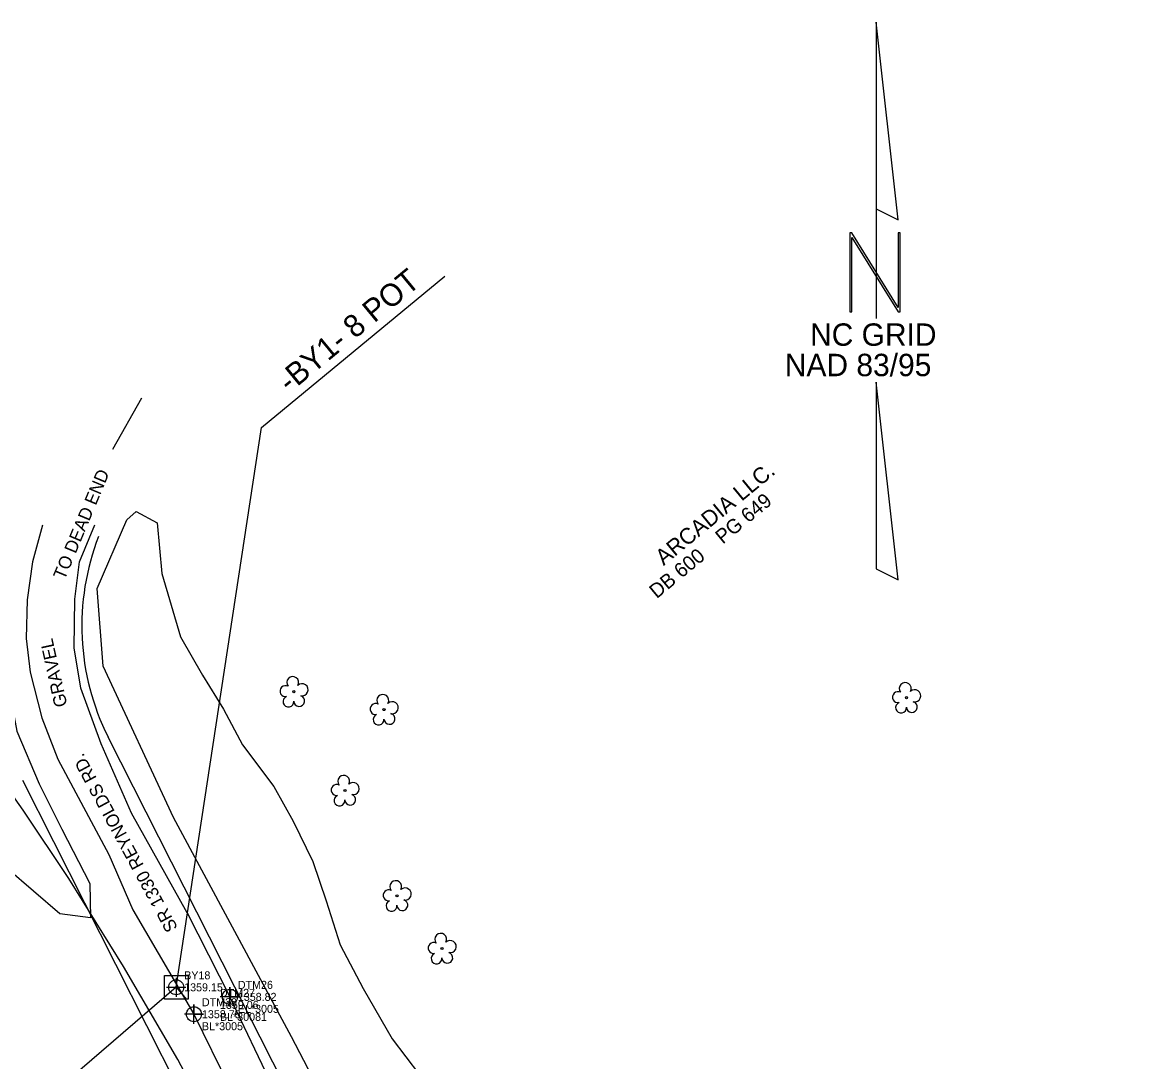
# Model space of a CAD drawing. Extents: x 1435573 to 1437263, y 981340 to 982884.
# Drawn here: x 1436335.7 to 1436683.9, y 982559.5 to 982884.4 of the extents above; entities that cross this region are included whole.
import ezdxf

# ---------------------------------------------------------------- set-up
doc = ezdxf.new("R2010")
doc.units = 0
for name, color, linetype in [('Cogo Default Point CELL', 7, 'Continuous'), ('COGO Default Point Elevation', 7, 'Continuous'), ('COGO Default Point Number', 7, 'Continuous'), ('CTL North Arrow NAD 83 95 CELL', 7, 'Continuous'), ('CTL Supplemental Horizontal and Vertical CELL', 7, 'Continuous'), ('Exist DTM Crownline Cogo Comment', 7, 'Continuous'), ('Exist DTM Crownline Cogo Elevation', 7, 'Continuous'), ('Exist DTM Crownline Cogo Number', 7, 'Continuous'), ('Exist Horizontal Baseline Alignment', 7, 'Continuous'), ('Exist Horizontal Baseline Alignment Station Label', 7, 'Continuous'), ('Exist Horizontal Baseline Alignment Tick small', 7, 'Continuous'), ('Exist Other Culture Fence Line', 7, 'Continuous'), ('Exist Property Deed Book Text', 7, 'Continuous'), ('Exist Property Owner Text', 7, 'Continuous'), ('Exist Right of Way Line', 7, 'Continuous'), ('Exist Roads Soil', 7, 'Continuous'), ('Exist Roads Soil Cogo Comment', 7, 'Continuous'), ('Exist Roads Soil Cogo Elevation', 7, 'Continuous'), ('Exist Roads Soil Cogo Number', 7, 'Continuous'), ('Exist Roads Soil Cogo Point CELL', 7, 'Continuous'), ('Exist Roads Soil Leader', 7, 'Continuous'), ('Exist Roads Soil Text', 7, 'Continuous'), ('Exist Vegetation Tree CELL', 7, 'Continuous'), ('Exist Vegetation Woods Line', 7, 'Continuous')]:
    doc.layers.add(name, color=color, linetype=linetype)

# ---------------------------------------------------------------- blocks, each defined once
blk = doc.blocks.new('CTL SUPPLEMENTAL HORIZONTAL AND VERTICAL')
at = {"layer": 'CTL Supplemental Horizontal and Vertical CELL'}
blk.add_line((0, 0), (0, 0), dxfattribs=at)
blk.add_lwpolyline([(-0.0735, 0.074), (0.07475, 0.074), (0.07475, -0.0745), (-0.0735, -0.0745)], close=True, dxfattribs=at)
blk = doc.blocks.new('CTL NORTH ARROW NAD 83 95')
at = {"layer": 'CTL North Arrow NAD 83 95 CELL'}
for points in [[(-0.003, 1.7458), (-0.003, 0.5793), (0.1345, 0.5105)], [(-0.1675, -0.0653), (-0.1537, -0.0653), (-0.1537, 0.4012), (0.1345, -0.0653), (0.1482, -0.0653), (0.1482, 0.4285), (0.1345, 0.4285), (0.1345, -0.038), (-0.1537, 0.4285), (-0.1675, 0.4285)], [(-0.003, -1.671), (0.1345, -1.7392), (-0.003, -0.5045)]]:
    blk.add_lwpolyline(points, close=True, dxfattribs=at)
blk.add_lwpolyline([(-0.003, 0.5793), (-0.003, -0.1067)], dxfattribs=at)
for s, p in [('NC GRID', (-0.4154, -0.2767)), ('NAD 83/95', (-0.5731, -0.4667))]:
    blk.add_text(s, height=0.14, dxfattribs=at).set_placement(p)

msp = doc.modelspace()

# ---------------------------------------------------------------- linework, layer by layer
at = {"layer": 'Cogo Default Point CELL'}
for points in [[(1436383.8, 982585.77), (1436383.8, 982582.77)], [(1436380.8, 982582.77), (1436383.8, 982582.77)], [(1436383.8, 982582.77), (1436386.8, 982582.77)], [(1436383.8, 982582.77), (1436383.8, 982579.77)]]:
    msp.add_lwpolyline(points, dxfattribs=at)
msp.add_circle((1436383.8, 982582.77), 2.34, dxfattribs=at)
at = {"layer": 'Exist Horizontal Baseline Alignment'}
msp.add_line((1436383.8, 982582.77), (1436220.79, 982442.59), dxfattribs=at)
at = {"layer": 'Exist Horizontal Baseline Alignment Station Label'}
for p, q in [((1436410.49, 982757.79), (1436467.76, 982805.06)), ((1436383.8, 982582.77), (1436410.49, 982757.79))]:
    msp.add_line(p, q, dxfattribs=at)
at = {"layer": 'Exist Horizontal Baseline Alignment Tick small'}
msp.add_line((1436383.8, 982582.77), (1436387.06, 982578.98), dxfattribs=at)
at = {"layer": 'Exist Other Culture Fence Line'}
msp.add_lwpolyline([(1436407.45, 982513.75), (1436396.08, 982537.77), (1436384.33, 982560.23), (1436367.33, 982589.31), (1436350.22, 982616.82), (1436336.01, 982638.12), (1436324.12, 982654.83), (1436316.59, 982679.36), (1436311.21, 982691.99), (1436311.43, 982712.74), (1436311.84, 982730.67)], dxfattribs=at)
at = {"layer": 'Exist Right of Way Line'}
for p, q in [((1436362.49, 982661.08), (1436453.17, 982481.97)), ((1436335.73, 982647.53), (1436408.6, 982503.6))]:
    msp.add_line(p, q, dxfattribs=at)
msp.add_arc((1436431.59, 982695.7), 77.28, 158.7705, 206.6391, dxfattribs=at)
at = {"layer": 'Exist Roads Soil'}
for p, q in [((1436423.3, 982532.29), (1436400.57, 982579.79)), ((1436389.35, 982574.36), (1436412.81, 982526.49))]:
    msp.add_line(p, q, dxfattribs=at)
for points in [[(1436342.05, 982727.23), (1436338.86, 982715.75), (1436337.28, 982703.86), (1436336.9, 982691.84), (1436338.16, 982681.24), (1436341.87, 982667), (1436346.86, 982654.14), (1436354.05, 982640.61), (1436362.77, 982624.29), (1436370.25, 982607.02)], [(1436387.28, 982606.05), (1436369.84, 982637.26), (1436360.31, 982658.92), (1436354.03, 982676.29), (1436351.96, 982688.94), (1436352.09, 982704.07), (1436353.56, 982715.77), (1436358.41, 982727.38)], [(1436370.25, 982607.02), (1436389.35, 982574.36)], [(1436387.28, 982606.05), (1436400.57, 982579.79)]]:
    msp.add_lwpolyline(points, dxfattribs=at)
at = {"layer": 'Exist Roads Soil Cogo Point CELL'}
for points in [[(1436400.57, 982576.79), (1436400.57, 982582.79), (1436400.57, 982579.79), (1436403.57, 982579.79), (1436397.57, 982579.79)], [(1436389.35, 982571.36), (1436389.35, 982577.36), (1436389.35, 982574.36), (1436392.35, 982574.36), (1436386.35, 982574.36)]]:
    msp.add_lwpolyline(points, dxfattribs=at)
for centre in [(1436400.57, 982579.79), (1436389.35, 982574.36)]:
    msp.add_circle(centre, 2.34, dxfattribs=at)
at = {"layer": 'Exist Roads Soil Leader'}
msp.add_line((1436372.94, 982766.93), (1436363.91, 982750.84), dxfattribs=at)
at = {"layer": 'Exist Vegetation Tree CELL'}
for p, q in [((1436420.59, 982675.19), (1436420.59, 982675.19)), ((1436612, 982673.31), (1436612, 982673.31)), ((1436448.75, 982669.58), (1436448.75, 982669.58)), ((1436436.54, 982644.31), (1436436.54, 982644.31)), ((1436452.8, 982611.35), (1436452.8, 982611.35)), ((1436466.86, 982594.91), (1436466.86, 982594.91))]:
    msp.add_line(p, q, dxfattribs=at)
for centre in [(1436420.59, 982675.19), (1436612, 982673.31), (1436448.75, 982669.58), (1436436.54, 982644.31), (1436452.8, 982611.35), (1436466.86, 982594.91)]:
    msp.add_circle(centre, 0.326, dxfattribs=at)
for centre, radius, start, end in [((1436420.2, 982678.06), 1.86, 330.1651, 219.7134), ((1436417.98, 982675.34), 1.73, 62.6636, 279.3457), ((1436423.14, 982675.78), 1.9, 257.1011, 134.1999), ((1436609.39, 982673.46), 1.73, 62.6636, 279.3457), ((1436611.61, 982676.18), 1.86, 330.1651, 219.7134), ((1436614.55, 982673.9), 1.9, 257.1011, 134.1999), ((1436418.88, 982672.07), 1.69, 111.5671, 6.231), ((1436422.26, 982672.29), 1.7, 181.2822, 74.56), ((1436446.15, 982669.73), 1.73, 62.6636, 279.3457), ((1436448.37, 982672.45), 1.86, 330.1651, 219.7134), ((1436451.3, 982670.16), 1.9, 257.1011, 134.1999), ((1436610.3, 982670.19), 1.69, 111.5671, 6.231), ((1436613.67, 982670.41), 1.7, 181.2822, 74.56), ((1436447.05, 982666.45), 1.69, 111.5671, 6.231), ((1436450.43, 982666.68), 1.7, 181.2822, 74.56), ((1436436.15, 982647.18), 1.86, 330.1651, 219.7134), ((1436433.93, 982644.46), 1.73, 62.6636, 279.3457), ((1436439.09, 982644.89), 1.9, 257.1011, 134.1999), ((1436434.83, 982641.18), 1.69, 111.5671, 6.231), ((1436438.21, 982641.41), 1.7, 181.2822, 74.56), ((1436452.41, 982614.23), 1.86, 330.1651, 219.7134), ((1436450.19, 982611.51), 1.73, 62.6636, 279.3457), ((1436455.35, 982611.94), 1.9, 257.1011, 134.1999), ((1436451.09, 982608.23), 1.69, 111.5671, 6.231), ((1436454.47, 982608.45), 1.7, 181.2822, 74.56), ((1436466.48, 982597.79), 1.86, 330.1651, 219.7134), ((1436464.26, 982595.07), 1.73, 62.6636, 279.3457), ((1436469.41, 982595.5), 1.9, 257.1011, 134.1999), ((1436465.16, 982591.79), 1.69, 111.5671, 6.231), ((1436468.53, 982592.01), 1.7, 181.2822, 74.56)]:
    msp.add_arc(centre, radius, start, end, dxfattribs=at)
at = {"layer": 'Exist Vegetation Woods Line'}
for points in [[(1436329.94, 982727.52), (1436327.49, 982697.57), (1436333.96, 982662.84), (1436341.02, 982646.4), (1436348.03, 982632.21), (1436356.84, 982615.2), (1436357.01, 982604.5), (1436347.42, 982605.75), (1436330.99, 982619.92), (1436315.96, 982633.27), (1436299.42, 982650.22), (1436281.92, 982666.07), (1436261.65, 982682.01), (1436239.77, 982694.3), (1436224.35, 982705.66), (1436215.08, 982714.28), (1436216.7, 982722.96), (1436223.1, 982732.29)], [(1436709.86, 982445.43), (1436673.85, 982448.35), (1436636.59, 982451.74), (1436599.44, 982457.01), (1436556.56, 982467.51), (1436518.42, 982473.6), (1436488.34, 982478.47), (1436470.36, 982485.46), (1436455.98, 982497.86), (1436419.79, 982567.3), (1436382.96, 982635.88), (1436360.99, 982683.15), (1436359.14, 982707.48), (1436368.37, 982728.89), (1436371.28, 982731.54), (1436377.82, 982727.96)], [(1436377.82, 982727.96), (1436379.34, 982712.13), (1436385.14, 982692.34), (1436392.07, 982680.38), (1436398.6, 982669.67), (1436404.49, 982658.57), (1436414.27, 982645.56), (1436420.33, 982634.75), (1436426.54, 982622.07), (1436430.68, 982609.82), (1436435.07, 982596.06), (1436442.27, 982582.35), (1436451.33, 982566.69), (1436459.82, 982555.42)]]:
    msp.add_lwpolyline(points, dxfattribs=at)

# ---------------------------------------------------------------- block references
at = {"layer": 'CTL North Arrow NAD 83 95 CELL', "xscale": 50, "yscale": 50}
msp.add_blockref('CTL NORTH ARROW NAD 83 95', (1436602.64, 982797.14), dxfattribs=at)
at = {"layer": 'CTL Supplemental Horizontal and Vertical CELL', "xscale": 50, "yscale": 50}
msp.add_blockref('CTL SUPPLEMENTAL HORIZONTAL AND VERTICAL', (1436383.8, 982582.77), dxfattribs=at)

# ---------------------------------------------------------------- texts
at = {"layer": 'COGO Default Point Elevation'}
msp.add_text('1359.15', height=2.5, dxfattribs=at).set_placement((1436386.3, 982581.52))
at = {"layer": 'COGO Default Point Number'}
msp.add_text('BY18', height=2.5, dxfattribs=at).set_placement((1436386.3, 982585.27))
at = {"layer": 'Exist DTM Crownline Cogo Comment'}
msp.add_text('BL*30081', height=2.5, dxfattribs=at).set_placement((1436397.48, 982572.29))
at = {"layer": 'Exist DTM Crownline Cogo Elevation'}
msp.add_text('1359.06', height=2.5, dxfattribs=at).set_placement((1436397.48, 982576.04))
at = {"layer": 'Exist DTM Crownline Cogo Number'}
msp.add_text('DTM27', height=2.5, dxfattribs=at).set_placement((1436397.48, 982579.79))
at = {"layer": 'Exist Horizontal Baseline Alignment Station Label'}
msp.add_text('-BY1- 8 POT  ', height=7, rotation=39.5399, dxfattribs=at).set_placement((1436419.19, 982768.41))
at = {"layer": 'Exist Property Deed Book Text'}
msp.add_text('DB 600    PG 649', height=4.5, rotation=39.5399, dxfattribs=at).set_placement((1436533.96, 982704.1))
at = {"layer": 'Exist Property Owner Text'}
msp.add_text('ARCADIA LLC.', height=5, rotation=39.5399, dxfattribs=at).set_placement((1436536.13, 982714.43))
at = {"layer": 'Exist Roads Soil Cogo Comment'}
for s, p in [('EL*3005', (1436403.07, 982574.79)), ('BL*3005', (1436391.85, 982569.36))]:
    msp.add_text(s, height=2.5, dxfattribs=at).set_placement(p)
at = {"layer": 'Exist Roads Soil Cogo Elevation'}
for s, p in [('1358.82', (1436403.07, 982578.54)), ('1358.75', (1436391.85, 982573.11))]:
    msp.add_text(s, height=2.5, dxfattribs=at).set_placement(p)
at = {"layer": 'Exist Roads Soil Cogo Number'}
for s, p in [('DTM26', (1436403.07, 982582.29)), ('DTM29', (1436391.85, 982576.86))]:
    msp.add_text(s, height=2.5, dxfattribs=at).set_placement(p)
at = {"layer": 'Exist Roads Soil Text'}
for s, rotation, p in [('TO DEAD END', 67.3073, (1436348.93, 982709.9)), ('GRAVEL', 102.5211, (1436349.82, 982670.85)), ('SR 1330 REYNOLDS RD.', 118.4613, (1436384.42, 982601.37))]:
    msp.add_text(s, height=4, rotation=rotation, dxfattribs=at).set_placement(p)

doc.saveas('drawing.dxf')
